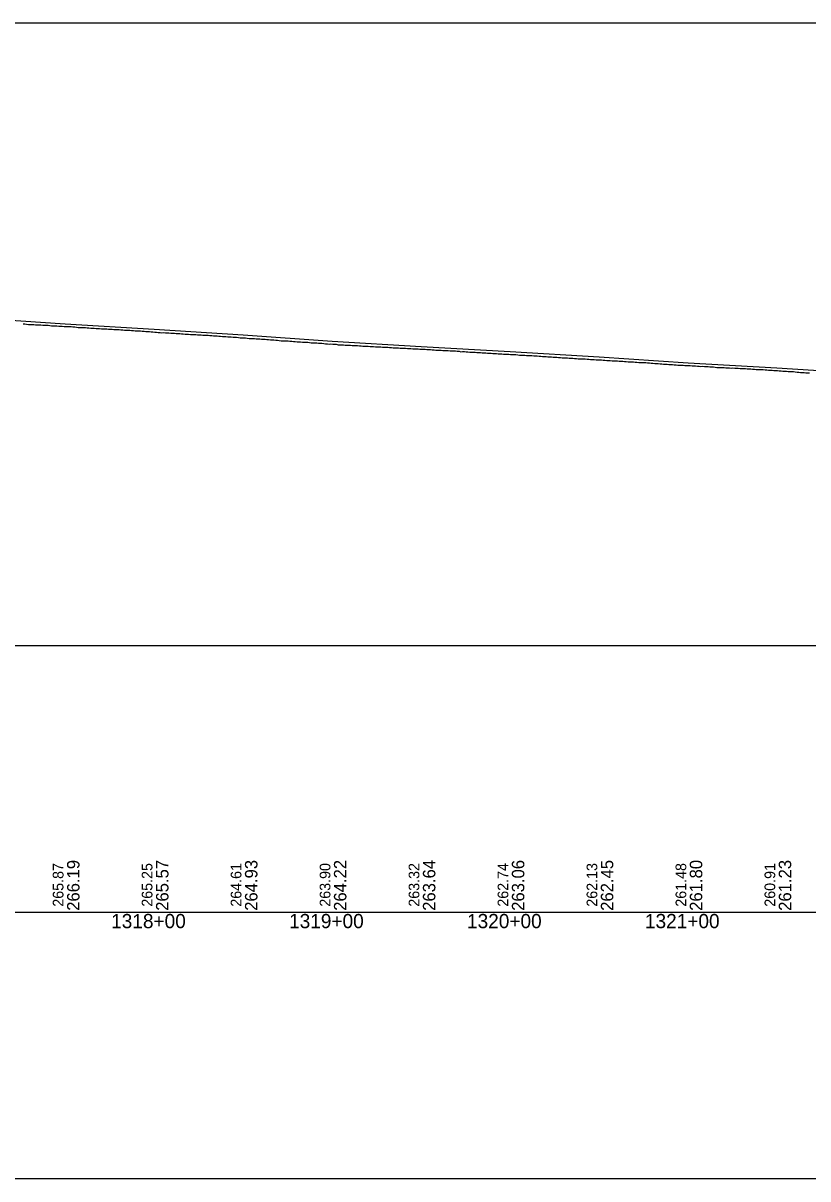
# Model space of a CAD drawing. Extents: x -3627 to 47473, y 2850 to 4350.
# Drawn here: x 19104 to 19545, y 2850 to 3500 of the extents above; entities that cross this region are included whole.
import ezdxf

# ---------------------------------------------------------------- set-up
doc = ezdxf.new("R2010")
doc.units = 0
for name, color, linetype in [('RD_DDB_Profile_EX', 7, 'Continuous'), ('RD_DDB_Profile_PR', 7, 'Continuous'), ('RD_DDB_StaTX', 7, 'Continuous'), ('RD_DDB_StripGrade', 7, 'Continuous'), ('RD_GPK_Profile_Cell', 7, 'Continuous'), ('RD_SHT_ShtClip', 7, 'Continuous')]:
    doc.layers.add(name, color=color, linetype=linetype)

msp = doc.modelspace()

# ---------------------------------------------------------------- linework, layer by layer
at = {"layer": 'RD_DDB_Profile_EX'}
for points in [[(19103.632069, 3330.82642), (19104.633392, 3330.78519), (19105.633523, 3330.7357), (19106.634848, 3330.576025), (19107.634977, 3330.53578), (19108.636304, 3330.526115), (19109.635009, 3330.41766), (19110.629988, 3330.37681), (19111.636463, 3330.326905), (19112.63144, 3330.276905), (19113.637916, 3330.227), (19114.632892, 3330.136125), (19115.639368, 3330.08621), (19116.632927, 3330.036305), (19117.639409, 3330.040955), (19118.634379, 3330.000045), (19119.629348, 3329.836395), (19120.635829, 3329.777405), (19121.630797, 3329.777405), (19122.635873, 3329.727615), (19123.630837, 3329.64571), (19124.637324, 3329.595785), (19125.632286, 3329.477715), (19126.638774, 3329.36879), (19127.633734, 3329.35977), (19128.633846, 3329.355265), (19129.633781, 3329.337025), (19130.633902, 3329.287555), (19131.634966, 3329.15523), (19132.636292, 3329.104915), (19133.636209, 3328.95467), (19134.632316, 3328.8819), (19135.632235, 3328.845415), (19136.633559, 3328.80839), (19137.634614, 3328.808075), (19138.6296, 3328.74888), (19139.630658, 3328.544655), (19140.631988, 3328.54428), (19141.637007, 3328.412955), (19142.63317, 3328.413025), (19143.633056, 3328.41283), (19144.634376, 3328.321935), (19145.635424, 3328.22184), (19146.63044, 3328.20307), (19147.631491, 3328.11233), (19148.632817, 3328.07156), (19149.632663, 3328.04284), (19150.635189, 3327.99257), (19151.628747, 3327.91177), (19152.630072, 3327.87114), (19153.636211, 3327.790425), (19154.637526, 3327.7), (19155.6323, 3327.730785), (19156.633623, 3327.661325), (19157.633437, 3327.62085)], [(19157.633437, 3327.62085), (19158.635984, 3327.5), (19159.631058, 3327.420715), (19160.630864, 3327.341155), (19161.633428, 3327.30074), (19162.633218, 3327.30051), (19163.629559, 3327.30059), (19164.62935, 3327.14007), (19165.630677, 3327.08002), (19166.630534, 3327.030795), (19167.636916, 3326.98087), (19168.630475, 3326.880965), (19169.638105, 3326.890995), (19170.631665, 3326.84108), (19171.631817, 3326.76226), (19172.632854, 3326.571775), (19173.633005, 3326.522345), (19174.634043, 3326.531845), (19175.634193, 3326.451675), (19176.629253, 3326.301675), (19177.634165, 3326.24216), (19178.629221, 3326.192155), (19179.629364, 3326.05216), (19180.630689, 3326.01333), (19181.63055, 3325.892845), (19182.636977, 3325.933395), (19183.632014, 3325.89291), (19184.630684, 3325.85286), (19185.632002, 3325.74561), (19186.632146, 3325.64642), (19187.633466, 3325.583645), (19188.633334, 3325.584385), (19189.628349, 3325.53438), (19190.634795, 3325.484465), (19191.628354, 3325.39391), (19192.628489, 3325.25363), (19193.629813, 3325.162655), (19194.628509, 3325.072255), (19195.629825, 3325.112755), (19196.63113, 3325.153905), (19197.626121, 3324.94078), (19198.631157, 3324.87646), (19199.631293, 3324.87706), (19200.632612, 3324.83983), (19201.631334, 3324.75), (19202.626305, 3324.700005), (19203.628779, 3324.640355), (19204.635255, 3324.549625), (19205.628814, 3324.44978), (19206.630135, 3324.43991), (19207.625119, 3324.480735), (19208.630169, 3324.38108), (19209.631482, 3324.23025), (19210.627631, 3324.11208), (19211.627525, 3324.111345), (19212.633989, 3324.111525), (19213.628981, 3323.99845), (19214.630305, 3323.88845), (19215.623864, 3323.779345), (19216.630322, 3323.77023), (19217.632814, 3323.728895), (19218.626373, 3323.62908), (19219.627697, 3323.487615), (19220.62271, 3323.478245), (19221.627706, 3323.36925), (19222.630206, 3323.359215), (19223.624945, 3323.319045), (19224.625998, 3323.149835), (19225.630989, 3323.068975), (19226.62718, 3323.05053), (19227.628232, 3323.050025), (19228.62179, 3322.91897), (19229.627968, 3322.860265), (19230.629016, 3322.68783), (19231.625202, 3322.638035), (19232.625077, 3322.59683), (19233.631254, 3322.5693), (19234.625991, 3322.47904), (19235.627313, 3322.428225), (19236.622049, 3322.37863), (19237.623102, 3322.30633), (19238.629279, 3322.25676), (19239.622839, 3322.16621), (19240.625338, 3322.075155), (19241.626389, 3321.99368), (19242.625078, 3321.87561), (19243.619808, 3321.90732), (19244.627435, 3321.866845), (19245.622155, 3321.70791), (19246.627194, 3321.598985), (19247.621911, 3321.426775), (19248.628124, 3321.40889), (19249.623098, 3321.377115), (19250.622962, 3321.31894), (19251.624021, 3321.27769), (19252.623888, 3321.237455), (19253.625209, 3321.137025), (19254.625076, 3321.096645), (19255.619754, 3320.96455), (19256.626008, 3320.88825), (19257.620936, 3320.847075)], [(19257.620936, 3320.847075), (19258.627197, 3320.788545), (19259.621861, 3320.68), (19260.620627, 3320.589365), (19261.621694, 3320.506525), (19262.622902, 3320.539765), (19263.623975, 3320.489535), (19264.622757, 3320.381595), (19265.617394, 3320.28183), (19266.623948, 3320.19044), (19267.618828, 3320.114925), (19268.625138, 3320.11533), (19269.620012, 3320.032275), (19270.625263, 3319.94092), (19271.620133, 3319.93249), (19272.621298, 3319.74991), (19273.621322, 3319.69962), (19274.621433, 3319.641825), (19275.622511, 3319.524805), (19276.622621, 3319.542045), (19277.617465, 3319.48378), (19278.622768, 3319.425735), (19279.618647, 3319.367645), (19280.618689, 3319.14201), (19281.613535, 3319.1503), (19282.620118, 3319.10038), (19283.621198, 3318.99187), (19284.616046, 3318.925275), (19285.622627, 3318.841975), (19286.616186, 3318.800345), (19287.618558, 3318.791745), (19288.617373, 3318.742365), (19289.618696, 3318.675345), (19290.62107, 3318.64161), (19291.619882, 3318.64223), (19292.621205, 3318.46674), (19293.614764, 3318.441895), (19294.622392, 3318.342095), (19295.617235, 3318.283835), (19296.617274, 3318.38344), (19297.623854, 3318.25016), (19298.61846, 3318.192055), (19299.619783, 3318.191625), (19300.619888, 3318.108685), (19301.62097, 3317.98362), (19302.615817, 3317.98363), (19303.615851, 3317.94993), (19304.622429, 3317.90001), (19305.618329, 3317.833475), (19306.618361, 3317.73308), (19307.618467, 3317.70883), (19308.618496, 3317.67496), (19309.614399, 3317.63343), (19310.620977, 3317.583535), (19311.615579, 3317.43377), (19312.615616, 3317.41672), (19313.621957, 3317.40884), (19314.617846, 3317.37556), (19315.617883, 3317.28344), (19316.61775, 3317.217835), (19317.619071, 3317.21722), (19318.613671, 3317.225755), (19319.62002, 3317.08433), (19320.614854, 3317.026135), (19321.621209, 3316.96833), (19322.615796, 3316.876755), (19323.617123, 3316.8844), (19324.61698, 3316.885225), (19325.617041, 3316.784835), (19326.611626, 3316.651295), (19327.619253, 3316.585285), (19328.619314, 3316.576755), (19329.61919, 3316.551785), (19330.621526, 3316.50959), (19331.615085, 3316.417725), (19332.621466, 3316.40183), (19333.616272, 3316.34381), (19334.61736, 3316.25163), (19335.617226, 3316.160205), (19336.618547, 3316.15188), (19337.613115, 3316.07807), (19338.619503, 3315.978425), (19339.613063, 3315.92855), (19340.620692, 3315.90253), (19341.614252, 3315.83682), (19342.615341, 3315.802405), (19343.61643, 3315.760785), (19344.616531, 3315.760545), (19345.611084, 3315.61068), (19346.61871, 3315.602985), (19347.612269, 3315.59524), (19348.618686, 3315.472165), (19349.612247, 3315.21115), (19350.61455, 3315.23747), (19351.614412, 3315.24198), (19352.61453, 3315.15683), (19353.610271, 3315.04927), (19354.616696, 3314.965195), (19355.616814, 3314.86466), (19356.619113, 3314.89074), (19357.612673, 3314.85651)], [(19357.612673, 3314.85651), (19358.613993, 3314.805795), (19359.615313, 3314.73926), (19360.6101, 3314.68138), (19361.615507, 3314.555405), (19362.61682, 3314.578515), (19363.618133, 3314.51998), (19364.612934, 3314.461995), (19365.614256, 3314.3694), (19366.61432, 3314.327025), (19367.609138, 3314.28515), (19368.61046, 3314.26834), (19369.61706, 3314.16847), (19370.618374, 3314.051445), (19371.613208, 3313.97683), (19372.613249, 3313.92611), (19373.615613, 3313.833735), (19374.610461, 3313.792055), (19375.611793, 3313.832915), (19376.613124, 3313.73208), (19377.618385, 3313.665635), (19378.613248, 3313.632445), (19379.614572, 3313.631605), (19380.615896, 3313.5478), (19381.610777, 3313.439295), (19382.61211, 3313.338515), (19383.612102, 3313.296525), (19384.613426, 3313.319755), (19385.61354, 3313.203635), (19386.614866, 3313.11995), (19387.616191, 3313.13651), (19388.60975, 3313.05412), (19389.611075, 3313.027125), (19390.612401, 3312.876285), (19391.613726, 3312.843235), (19392.608667, 3312.834345), (19393.615172, 3312.75785), (19394.615111, 3312.666025), (19395.610057, 3312.583895), (19396.611384, 3312.497145), (19397.612712, 3312.45517), (19398.612832, 3312.360205), (19399.614161, 3312.3144), (19400.614078, 3312.28187), (19401.609048, 3312.10913), (19402.61553, 3312.082025), (19403.610498, 3312.082025), (19404.611829, 3311.981235), (19405.611732, 3311.91226), (19406.611863, 3311.831565), (19407.613187, 3311.789945), (19408.61451, 3311.70768), (19409.609502, 3311.69845), (19410.615966, 3311.648575), (19411.615851, 3311.598055), (19412.610578, 3311.48915), (19413.611902, 3311.407015), (19414.606629, 3311.31098), (19415.613088, 3311.220405), (19416.61414, 3311.229265), (19417.609141, 3311.23855), (19418.610196, 3311.17887), (19419.616649, 3311.129015), (19420.610209, 3311.042025), (19421.612708, 3310.991275), (19422.612578, 3310.8874), (19423.612447, 3310.87934), (19424.613767, 3310.81921), (19425.614815, 3310.646905), (19426.609829, 3310.66565), (19427.616005, 3310.64736), (19428.611013, 3310.578695), (19429.610883, 3310.49058), (19430.61339, 3310.3681), (19431.612073, 3310.31597), (19432.614575, 3310.337435), (19433.614436, 3310.23688), (19434.610645, 3310.137075), (19435.615627, 3310.106145), (19436.610369, 3310.069025), (19437.611693, 3310.00877), (19438.610379, 3309.96937), (19439.612879, 3309.937505), (19440.606438, 3309.83767), (19441.614065, 3309.76933), (19442.613932, 3309.609305), (19443.610128, 3309.56891), (19444.615125, 3309.506615), (19445.611309, 3309.556775), (19446.611184, 3309.437575), (19447.609878, 3309.32002), (19448.612371, 3309.27874), (19449.60593, 3309.178915), (19450.613558, 3309.097845), (19451.607117, 3309.11654), (19452.609614, 3309.116145), (19453.608304, 3309.03921), (19454.610796, 3308.988685), (19455.604354, 3308.87032), (19456.610814, 3308.68898), (19457.611865, 3308.68862)], [(19457.611865, 3308.68862), (19458.605425, 3308.64805), (19459.613054, 3308.57987), (19460.606613, 3308.51159), (19461.607933, 3308.42927), (19462.608069, 3308.289405), (19463.610559, 3308.229625), (19464.609256, 3308.23072), (19465.610578, 3308.143005), (19466.605571, 3308.02071), (19467.610604, 3307.980265), (19468.605593, 3307.921055), (19469.606917, 3307.78876), (19470.608205, 3307.739805), (19471.608103, 3307.68002), (19472.609427, 3307.61995), (19473.609558, 3307.57095), (19474.609445, 3307.579565), (19475.604442, 3307.52956), (19476.610903, 3307.42971), (19477.605898, 3307.37971), (19478.606953, 3307.379315), (19479.607082, 3307.30261), (19480.608409, 3307.27019), (19481.607108, 3307.189755), (19482.608428, 3307.057525), (19483.603423, 3307.007525), (19484.609885, 3306.966875), (19485.604605, 3307.00794), (19486.611072, 3306.939665), (19487.606059, 3306.889665), (19488.605953, 3306.7891), (19489.606086, 3306.7308), (19490.607409, 3306.73001), (19491.60754, 3306.69011), (19492.607435, 3306.56193), (19493.603582, 3306.398925), (19494.61005, 3306.321525), (19495.603609, 3306.40339), (19496.610082, 3306.37188), (19497.605062, 3306.26273), (19498.606389, 3306.221025), (19499.605096, 3306.09049), (19500.607573, 3306.04912), (19501.602556, 3306.03078), (19502.607604, 3306.062825), (19503.602583, 3305.981115), (19504.609058, 3305.972135), (19505.604035, 3305.93127), (19506.603939, 3305.84901), (19507.604071, 3305.781605), (19508.606547, 3305.76271), (19509.605257, 3305.686825), (19510.60658, 3305.513095), (19511.601556, 3305.572225), (19512.608033, 3305.531505), (19513.601591, 3305.472585), (19514.609218, 3305.34113), (19515.602777, 3305.218475), (19516.604101, 3305.249675), (19517.602824, 3305.24161), (19518.605287, 3305.181985), (19519.605411, 3305.164945), (19520.605331, 3305.07327), (19521.601434, 3304.9735), (19522.606522, 3304.823865), (19523.607839, 3304.732065), (19524.602806, 3304.763925), (19525.603865, 3304.71793), (19526.60519, 3304.635025), (19527.603907, 3304.55015), (19528.605223, 3304.449465), (19529.6077, 3304.35304), (19530.601259, 3304.303265), (19531.602583, 3304.27997), (19532.602466, 3304.17935), (19533.603769, 3304.098905), (19534.605093, 3304.057475), (19535.604973, 3303.988395), (19536.601146, 3304.010745), (19537.601027, 3303.87869), (19538.60748, 3303.71612), (19539.602486, 3303.6568), (19540.603537, 3303.578435), (19541.60486, 3303.54646), (19542.598419, 3303.518415), (19543.604863, 3303.3498), (19544.607369, 3303.308515), (19545.600928, 3303.23698)]]:
    msp.add_lwpolyline(points, dxfattribs=at)
at = {"layer": 'RD_DDB_Profile_PR'}
msp.add_lwpolyline([(18627.33, 3362.71), (18677.33, 3359.498), (18727.33, 3356.3775), (18777.33, 3353.3695), (18827.33, 3350.169), (18877.33, 3346.8805), (18927.33, 3343.779), (18977.33, 3340.595), (19027.33, 3337.471), (19077.33, 3334.272), (19127.33, 3330.9625), (19177.33, 3327.86), (19227.33, 3324.65), (19277.33, 3321.1005), (19327.33, 3318.204), (19377.33, 3315.2845), (19427.33, 3312.2525), (19477.33, 3308.9935), (19527.33, 3306.1735), (19577.33, 3302.878)], dxfattribs=at)
at = {"layer": 'RD_GPK_Profile_Cell'}
msp.add_line((1000, 3000), (46705.077602, 3000), dxfattribs=at)
at = {"layer": 'RD_SHT_ShtClip'}
for points in [[(18953.33, 3500), (18953.33, 3000), (20453.33, 3000), (20453.33, 3000), (20453.33, 3500), (20453.33, 3500)], [(18933.33, 3150), (20473.33, 3150), (20473.33, 2850), (18933.33, 2850)]]:
    msp.add_lwpolyline(points, close=True, dxfattribs=at)

# ---------------------------------------------------------------- texts
at = {"layer": 'RD_DDB_StaTX'}
for s, p in [('1318+00', (19153.125471, 2991)), ('1319+00', (19253.125471, 2991)), ('1320+00', (19353.125471, 2991)), ('1321+00', (19453.125471, 2991))]:
    msp.add_text(s, height=8, dxfattribs=at).set_placement(p)
at = {"layer": 'RD_DDB_StripGrade'}
for s, height, p in [('263.64', 7, (19335.33, 3000.75)), ('261.80', 7, (19485.33, 3000.75)), ('265.87', 6, (19126.33, 3003.073688)), ('266.19', 7, (19135.33, 3000.75)), ('265.25', 6, (19176.33, 3003.073688)), ('265.57', 7, (19185.33, 3000.75)), ('264.61', 6, (19226.33, 3003.073688)), ('264.93', 7, (19235.33, 3000.75)), ('263.90', 6, (19276.33, 3003.073688)), ('264.22', 7, (19285.33, 3000.75)), ('263.32', 6, (19326.33, 3003.073688)), ('262.74', 6, (19376.33, 3003.073688)), ('263.06', 7, (19385.33, 3000.75)), ('262.13', 6, (19426.33, 3003.073688)), ('262.45', 7, (19435.33, 3000.75)), ('261.48', 6, (19476.33, 3003.073688)), ('260.91', 6, (19526.33, 3003.073688)), ('261.23', 7, (19535.33, 3000.75))]:
    msp.add_text(s, height=height, rotation=90, dxfattribs=at).set_placement(p)

doc.saveas('drawing.dxf')
